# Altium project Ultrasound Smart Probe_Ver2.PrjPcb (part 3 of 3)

## Sheet Sht07--High Voltage Power Supply.SchDoc: HVPS
size 431 x 279 mm; Date: Not shown in title block; ApprovedBy: Not shown in title block; CheckedBy: Not shown in title block; Author: Not shown in title block; CompanyName: Not shown in title block; DrawnBy: Bill.Xu; Engineer: Bill.Xu; Organization: Not shown in title block; Address1: Not shown in title block; Address2: Not shown in title block; Address3: Not shown in title block; Address4: Not shown in title block; DocumentNumber: 1; Revision: Use project parameter SCH_Rev; SheetNumber: 7; SheetTotal: 7; PageSetup: Record=PageOptions¦CenterHorizontal=True¦CenterVertical=True¦PrintScale=1.00¦XCorrection=1.00¦YCorrection=1.00¦PrintKind=0¦BorderSize=5000000¦LeftOffset=0¦BottomOffset=0¦Orientation=2¦PaperLength=1000¦PaperWidth=1000¦Scale=100¦PaperSource=15¦PrintQuality=600¦MediaType=1¦DitherType=10¦PaperKind=Letter¦PrintScaleMode=1
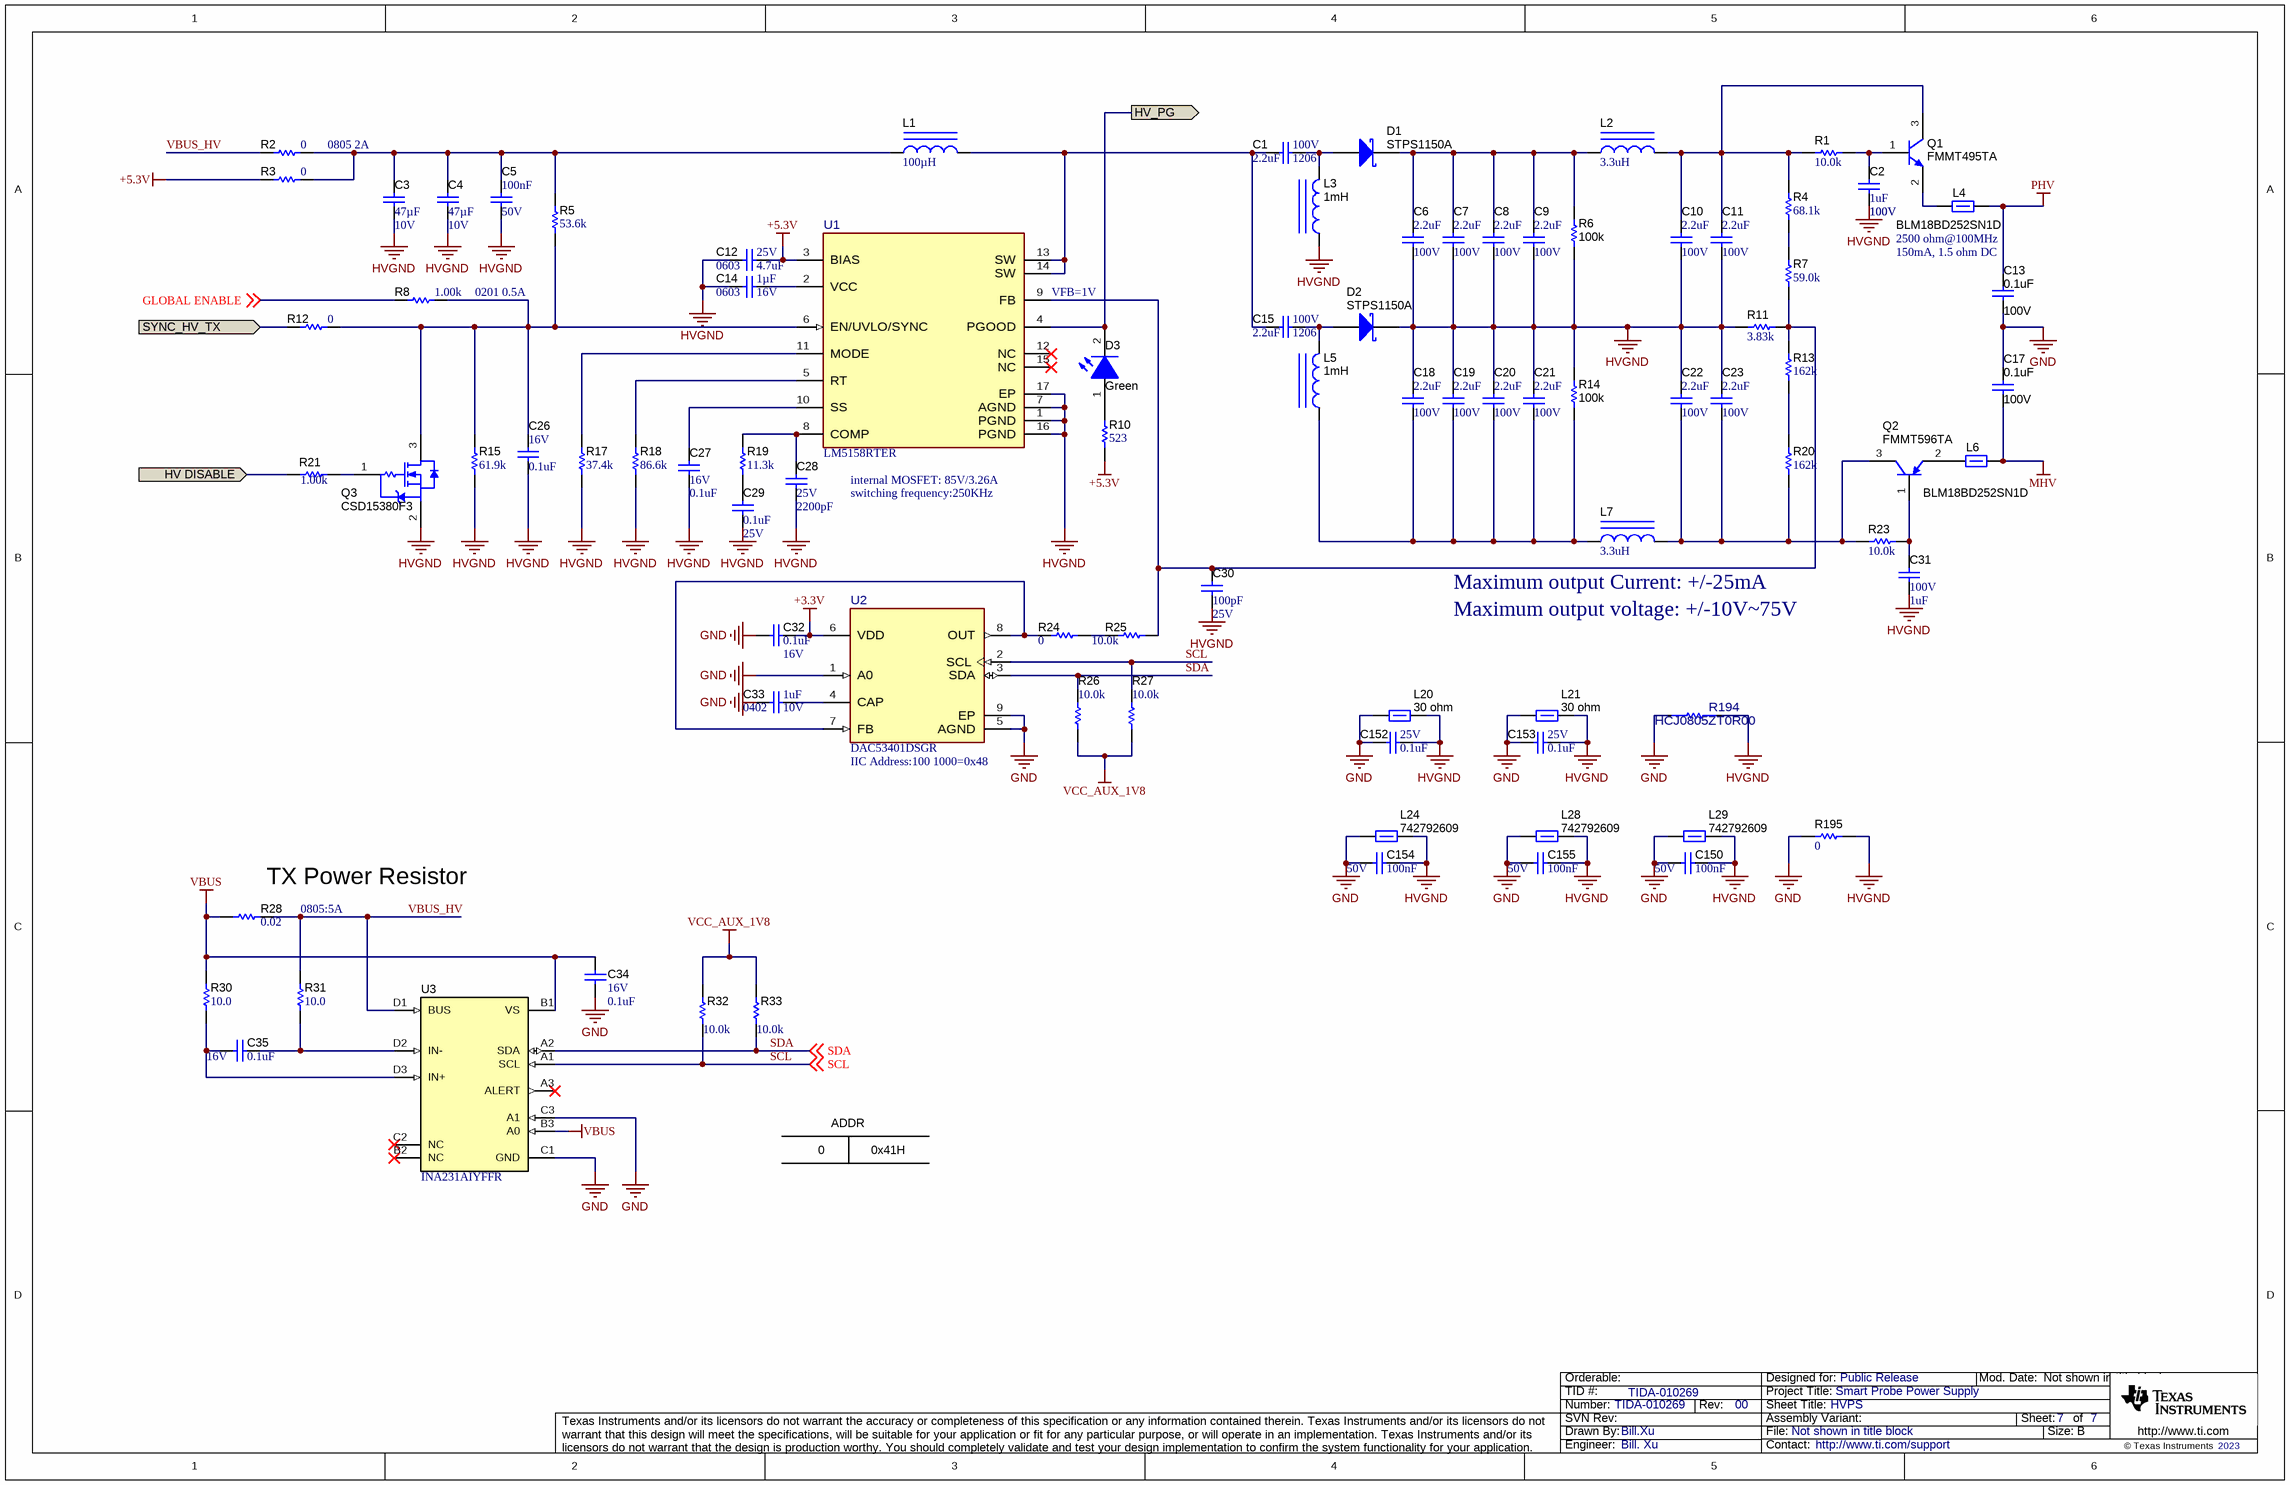
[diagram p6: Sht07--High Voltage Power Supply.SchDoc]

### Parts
C1  VDC_V: 100V  ValueDisplayed: 2.2uF  [1206_180]  (hidden comment: C3216X7S2A225K160AB)
C2  VDC_V: 100V  ValueDisplayed: 1uF  [0805_HV]  (hidden comment: C2012X7S2A105K125AB)
C3  VDC_V: 10V  ValueDisplayed: 47µF  [0805_HV]  (hidden comment: GRM21BR61A476ME15L)
C4  VDC_V: 10V  ValueDisplayed: 47µF  [0805_HV]  (hidden comment: GRM21BR61A476ME15L)
C5  Cap_F: 100nF  VDC_V: 50V  [0603]  (hidden comment: 885012206095)
C6  VDC_V: 100V  ValueDisplayed: 2.2uF  [1206_180]  (hidden comment: C3216X7S2A225K160AB)
C7  VDC_V: 100V  ValueDisplayed: 2.2uF  [1206_180]  (hidden comment: C3216X7S2A225K160AB)
C8  VDC_V: 100V  ValueDisplayed: 2.2uF  [1206_180]  (hidden comment: C3216X7S2A225K160AB)
C9  VDC_V: 100V  ValueDisplayed: 2.2uF  [1206_180]  (hidden comment: C3216X7S2A225K160AB)
C10  VDC_V: 100V  ValueDisplayed: 2.2uF  [1206_180]  (hidden comment: C3216X7S2A225K160AB)
C11  VDC_V: 100V  ValueDisplayed: 2.2uF  [1206_180]  (hidden comment: C3216X7S2A225K160AB)
C12  VDC_V: 25V  ValueDisplayed: 4.7uF  [0603]  (hidden comment: GRM188C81E475KE11D)
C13  VDC_V: 100V  ValueDisplayed: 0.1uF  [0603]  (hidden comment: GRM188R72A104KA35J)
C14  Cap_F: 1µF  VDC_V: 16V  [0603]  (hidden comment: GCM188R71C105KA64J)
C15  VDC_V: 100V  ValueDisplayed: 2.2uF  [1206_180]  (hidden comment: C3216X7S2A225K160AB)
C17  VDC_V: 100V  ValueDisplayed: 0.1uF  [0603]  (hidden comment: GRM188R72A104KA35J)
C18  VDC_V: 100V  ValueDisplayed: 2.2uF  [1206_180]  (hidden comment: C3216X7S2A225K160AB)
C19  VDC_V: 100V  ValueDisplayed: 2.2uF  [1206_180]  (hidden comment: C3216X7S2A225K160AB)
C20  VDC_V: 100V  ValueDisplayed: 2.2uF  [1206_180]  (hidden comment: C3216X7S2A225K160AB)
C21  VDC_V: 100V  ValueDisplayed: 2.2uF  [1206_180]  (hidden comment: C3216X7S2A225K160AB)
C22  VDC_V: 100V  ValueDisplayed: 2.2uF  [1206_180]  (hidden comment: C3216X7S2A225K160AB)
C23  VDC_V: 100V  ValueDisplayed: 2.2uF  [1206_180]  (hidden comment: C3216X7S2A225K160AB)
C26  VDC_V: 16V  ValueDisplayed: 0.1uF  [0201_033]  (hidden comment: C0603X6S1C104K030BC)
C27  VDC_V: 16V  ValueDisplayed: 0.1uF  [0201_033]  (hidden comment: C0603X6S1C104K030BC)
C28  VDC_V: 25V  ValueDisplayed: 2200pF  [0402]  (hidden comment: GRM155R71E222KA01D)
C29  VDC_V: 25V  ValueDisplayed: 0.1uF  [0402]  (hidden comment: GRM155R61E104KA87D)
C30  VDC_V: 25V  ValueDisplayed: 100pF  [0201_033]  (hidden comment: GRM033R71E101JA01D)
C31  VDC_V: 100V  ValueDisplayed: 1uF  [0805_HV]  (hidden comment: C2012X7S2A105K125AB)
C32  VDC_V: 16V  ValueDisplayed: 0.1uF  [0201_033]  (hidden comment: C0603X6S1C104K030BC)
C33  VDC_V: 10V  ValueDisplayed: 1uF  [0402]  (hidden comment: GRM155R61A105KE15D)
C34  VDC_V: 16V  ValueDisplayed: 0.1uF  [0201_033]  (hidden comment: C0603X6S1C104K030BC)
C35  VDC_V: 16V  ValueDisplayed: 0.1uF  [0201_033]  (hidden comment: C0603X6S1C104K030BC)
C150  Cap_F: 100nF  VDC_V: 50V  [0603]  (hidden comment: 885012206095)
C152  VDC_V: 25V  ValueDisplayed: 0.1uF  [0402]  (hidden comment: GRM155R61E104KA87D)
C153  VDC_V: 25V  ValueDisplayed: 0.1uF  [0402]  (hidden comment: GRM155R61E104KA87D)
C154  Cap_F: 100nF  VDC_V: 50V  [0603]  (hidden comment: 885012206095)
C155  Cap_F: 100nF  VDC_V: 50V  [0603]  (hidden comment: 885012206095)
D1  STPS1150A  [SMA]
D2  STPS1150A  [SMA]
D3  value Green  [LTST-C193_Green]  (hidden comment: LTST-C193KGKT-5A)
L1  ValueDisplayed: 100µH  [WE-LQS_8040]  (hidden comment: 74404084101)
L2  ValueDisplayed: 3.3uH  [WE-PMI_0806HS]  (hidden comment: 74479776233)
L3  ValueDisplayed: 1mH  [WE-TPC_4828]  (hidden comment: 744043102)
L4  BLM18BD252SN1D  [0603]
L5  ValueDisplayed: 1mH  [WE-TPC_4828]  (hidden comment: 744043102)
L6  BLM18BD252SN1D  [0603]
L7  ValueDisplayed: 3.3uH  [WE-PMI_0806HS]  (hidden comment: 74479776233)
L20  ValueDisplayed: 30 ohm  [0603]  (hidden comment: 742792609)
L21  ValueDisplayed: 30 ohm  [0603]  (hidden comment: 742792609)
L24  742792609  [0603]
L28  742792609  [0603]
L29  742792609  [0603]
Q1  FMMT495TA  [SOT-23]
Q2  FMMT596TA  [SOT-23]
Q3  CSD15380F3  [YJM0003A]
R1  ValueDisplayed: 10.0k  [0402]  (hidden comment: RK73H1ETTP1002F)
R2  ValueDisplayed: 0  [0805_HV]  (hidden comment: RC0805JR-070RL)
R3  ValueDisplayed: 0  [0805_HV]  (hidden comment: RC0805JR-070RL)
R4  ValueDisplayed: 68.1k  [0603]  (hidden comment: RC0603FR-0768K1L)
R5  ValueDisplayed: 53.6k  [0201]  (hidden comment: RC0201FR-0753K6L)
R6  ValueDisplayed: 100k  [0603]  (hidden comment: CRCW0603100KJNEAC)
R7  ValueDisplayed: 59.0k  [0603]  (hidden comment: RC0603FR-0759KL)
R8  ValueDisplayed: 1.00k  [0201]  (hidden comment: RC0201FR-7D1KL)
R10  ValueDisplayed: 523  [0402]  (hidden comment: CRCW0402523RFKED)
R11  ValueDisplayed: 3.83k  [0402]  (hidden comment: CRCW04023K83FKED)
R12  ValueDisplayed: 0  [0201]  (hidden comment: CRCW02010000Z0ED)
R13  ValueDisplayed: 162k  [0603]  (hidden comment: RC0603FR-07162KL)
R14  ValueDisplayed: 100k  [0603]  (hidden comment: CRCW0603100KJNEAC)
R15  ValueDisplayed: 61.9k  [0201]  (hidden comment: RC0201FR-0761K9L)
R17  ValueDisplayed: 37.4k  [0201]  (hidden comment: RC0201FR-0737K4L)
R18  ValueDisplayed: 86.6k  [0201]  (hidden comment: RC0201FR-0786K6L)
R19  ValueDisplayed: 11.3k  [0402]  (hidden comment: CRCW040211K3FKED)
R20  ValueDisplayed: 162k  [0603]  (hidden comment: RC0603FR-07162KL)
R21  ValueDisplayed: 1.00k  [0201]  (hidden comment: RC0201FR-7D1KL)
R23  ValueDisplayed: 10.0k  [0402]  (hidden comment: RK73H1ETTP1002F)
R24  ValueDisplayed: 0  [0201]  (hidden comment: CRCW02010000Z0ED)
R25  ValueDisplayed: 10.0k  [0201]  (hidden comment: RC0201FS-7D10KL)
R26  ValueDisplayed: 10.0k  [0201]  (hidden comment: RC0201FS-7D10KL)
R27  ValueDisplayed: 10.0k  [0201]  (hidden comment: RC0201FS-7D10KL)
R28  ValueDisplayed: 0.02  [WSLP0805]  (hidden comment: WSLP0805R0200FEB)
R30  ValueDisplayed: 10.0  [0201]  (hidden comment: RC0201FR-7D10RL)
R31  ValueDisplayed: 10.0  [0201]  (hidden comment: RC0201FR-7D10RL)
R32  ValueDisplayed: 10.0k  [0201]  (hidden comment: RC0201FS-7D10KL)
R33  ValueDisplayed: 10.0k  [0201]  (hidden comment: RC0201FS-7D10KL)
R194  HCJ0805ZT0R00  [FP-HCJ0805ZT0R00_0805-MFG]
R195  ValueDisplayed: 0  [0603]  (hidden comment: RC0603JR-070RL)
U1  LM5158RTER  [RTE0016K-MFG]
U2  DAC53401DSGR  [DSG0008A-MFG]
U3  INA231AIYFFR  [YFF0012AKAD]

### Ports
HV DISABLE (in), HV_PG (out), SYNC_HV_TX (in)

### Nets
+3.3V: C32.2 U2.6(VDD)
+5.3V: C12.1 R3.1 R10.1 U1.3(BIAS)
GND: C13.2 C17.1 C32.1 C33.2 C34.2 C150.2 C152.1 C153.1 C154.2 C155.2 L20.1 L21.1 L24.1 L28.1 L29.1 R194.1 R195.1 U2.1(A0) U2.5(AGND) U2.9(EP) U3.C1(GND) U3.C3(A1)
HVGND: C2.2 C3.2 C4.2 C5.2 C6.2 C7.2 C8.2 C9.2 C10.2 C11.2 C12.2 C14.2 C18.1 C19.1 C20.1 C21.1 C22.1 C23.1 C26.1 C27.1 C28.2 C29.2 C30.2 C31.2 C150.1 C152.2 C153.2 C154.1 C155.1 D2.1(K) L3.1 L20.2 L21.2 L24.2 L28.2 L29.2 Q3.2(S) R6.1 R11.1 R14.2 R15.1 R17.1 R18.1 R194.2 R195.2 U1.1(PGND) U1.7(AGND) U1.16(PGND) U1.17(EP)
MHV: C17.2 L6.2
PHV: C13.1 L4.2
VBUS: C34.1 R28.1 R30.2 U3.B1(VS) U3.B3(A0)
VCC_AUX_1V8: R26.1 R27.1 R32.2 R33.2
GLOBAL ENABLE: R8.1 ; off-sheet GLOBAL ENABLE
HV DISABLE: R21.1 ; port HV DISABLE
HV_PG: D3.2(K) U1.4(PGOOD) ; port HV_PG
SCL: R27.2 R32.1 U2.2(SCL) U3.A1(SCL) ; off-sheet SCL
SDA: R26.2 R33.1 U2.3(SDA) U3.A2(SDA) ; off-sheet SDA
SYNC_HV_TX: R12.1 ; port SYNC_HV_TX
VBUS_HV: R2.1 R28.2 R31.2 U3.D1(BUS)
NetC1_1: C1.1 C15.1 L1.2 U1.13(SW) U1.14(SW)
NetC1_2: C1.2 D1.2(A) L3.2
NetC2_1: C2.1 Q1.1(B) R1.2
NetC3_1: C3.1 C4.1 C5.1 L1.1 R2.2 R3.2 R5.2
NetC6_1: C6.1 C7.1 C8.1 C9.1 D1.1(K) L2.1 R6.2
NetC10_1: C10.1 C11.1 L2.2 Q1.3(C) R1.1 R4.2
NetC14_1: C14.1 U1.2(VCC)
NetC15_2: C15.2 D2.2(A) L5.2
NetC18_2: C18.2 C19.2 C20.2 C21.2 L5.1 L7.1 R14.1
NetC22_2: C22.2 C23.2 L7.2 Q2.3(C) R20.1 R23.1
NetC26_2: C26.2 Q3.3(D) R5.1 R8.2 R12.2 R15.2 U1.6(EN/UVLO/SYNC)
NetC27_2: C27.2 U1.10(SS)
NetC28_1: C28.1 R19.2 U1.8(COMP)
NetC29_1: C29.1 R19.1
NetC30_1: C30.1 R7.1 R11.2 R13.2 R25.1 U1.9(FB)
NetC31_1: C31.1 Q2.1(B) R23.2
NetC33_1: C33.1 U2.4(CAP)
NetC35_1: C35.1 R31.1 U3.D2(IN-)
NetC35_2: C35.2 R30.1 U3.D3(IN+)
NetD3_1: D3.1(A) R10.2
NetL4_1: L4.1 Q1.2(E)
NetL6_1: L6.1 Q2.2(E)
NetQ3_1: Q3.1(G) R21.2
NetR4_1: R4.1 R7.2
NetR13_1: R13.1 R20.2
NetR17_2: R17.2 U1.11(MODE)
NetR18_2: R18.2 U1.5(RT)
NetR24_1: R24.1 U2.7(FB) U2.8(OUT)
NetR24_2: R24.2 R25.2

Not connected (* = marked no-connect by the designer): U1 12(NC)* 15(NC)*; U3 A3(ALERT)* B2(NC)* C2(NC)*

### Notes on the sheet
- 0805 2A
- (near C1) 1206
- (near C2) 100V
- 0201 0.5A
- (near C14) 0603
- (near C12) 0603
- (near U1) VFB=1V
- 2500 ohm@100MHz
- 150mA, 1.5 ohm DC
- (near C15) 1206
- internal MOSFET: 85V/3.26A
- switching frequency:250KHz
- (near L7) Maximum output Current: +/-25mA
- Maximum output voltage: +/-10V~75V
- (near C33) 0402
- (near U2) IIC Address:100 1000=0x48
- (near R28) TX Power Resistor
- (near R28) 0805:5A
- 0
- ADDR
- 0x41H

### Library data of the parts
C1 C6-C11 C15 C18-C23 = CMP-0008724-2: CAP, CERM, 2.2 uF, 100 V, +/- 10%, X7S, 1206; Manufacturer: TDK; TaMin_C: -55°C; ESR_ohm: 5.718m; Polarized: N; SizeAreaWB_mm2: 10.92; Value1: 0.005718 ohm; U/M: EA; Value: 2.2uF; TaMax_C: 125°C; SizeZ_mm: 1.8; SizeX_mm: 3.2; SizeY_mm: 1.6; SizeArea_mm2: 5.12; Cap_F: 2.2µF; IRMS_A: 3.03632A; AEC Category: Q200
C2 = CMP-0007891-2: CAP, CERM, 1 uF, 100 V, +/- 10%, X7S, 0805; Manufacturer: TDK; TaMin_C: -55°C; ESR_ohm: 8.255m; Polarized: N; SizeAreaWB_mm2: 6.75; Value1: 0.008255 ohm; U/M: EA; Value: 1uF; TaMax_C: 125°C; SizeZ_mm: 1.45; SizeX_mm: 2; SizeY_mm: 1.25; Cap_Case: 0805; SizeArea_mm2: 2.5; Cap_F: 1µF; IRMS_A: 2.2744A; AEC Category: Q200
C3 C4 = CMP-0078699-1: CAP, CERM, 47 µF, 10 V,+/- 20%, X5R, 0805; Manufacturer: MuRata; TaMin_C: -55°C; Polarized: N; Green_Lifecycle: Active; SizeAreaWB_mm2: 6.75; Green_REACh: Passed; U/M: EA; Value: 47uF; TaMax_C: 85°C; SizeZ_mm: 1.45; SizeX_mm: 2; SizeY_mm: 1.25; Cap_Case: 0805; SizeArea_mm2: 2.5; AEC Category: Q200
C5 C150 C154 C155 = CMP-0006837-2: CAP, CERM, 0.1 uF, 50 V, +/- 10%, X7R, 0603; Manufacturer: Wurth Elektronik; TaMin_C: -55°C; Polarized: N; SizeAreaWB_mm2: 4.68; Value1: Unknown; U/M: EA; Value: 0.1uF; TaMax_C: 125°C; SizeZ_mm: 1; SizeX_mm: 1.6; SizeY_mm: 0.8; SizeArea_mm2: 1.28; AEC Category: Q200
C12 = CMP-0007297-3: CAP, CERM, 4.7 uF, 25 V, +/- 10%, X6S, 0603; Manufacturer: MuRata; TaMin_C: -55°C; Polarized: N; SizeAreaWB_mm2: 4.68; Value1: Unknown; U/M: EA; Value: 4.7uF; TaMax_C: 105°C; SizeZ_mm: 1; SizeX_mm: 1.6; SizeY_mm: 0.8; SizeArea_mm2: 1.28; Cap_F: 4.7µF; AEC Category: Q200
C13 C17 = CMP-0007470-5: CAP, CERM, 0.1 uF, 100 V, +/- 10%, X7R, 0603; Manufacturer: MuRata; TaMin_C: -55°C; Polarized: N; SizeAreaWB_mm2: 4.68; Value1: Unknown; U/M: EA; Value: 0.1uF; TaMax_C: 125°C; SizeZ_mm: 1; SizeX_mm: 1.6; SizeY_mm: 0.8; SizeArea_mm2: 1.28; Cap_F: 100nF; AEC Category: Q200
C14 = CMP-0079154-1: CAP, CERM, 1 µF, 16 V,+/- 10%, X7R, AEC-Q200 Grade 1, 0603; Manufacturer: MuRata; SizeAreaWB_mm2: 4.68; SizeArea_mm2: 1.28; AEC Qualified: Y; AEC Category: Q200; Value: 1uF; TaMax_C: 125°C; SizeZ_mm: 1; Polarized: N; TaMin_C: -55°C; SizeY_mm: 0.8; U/M: EA; SizeX_mm: 1.6
C26 C27 C32 C34 C35 = CMP-0009637-1: CAP, CERM, 0.1 uF, 16 V, +/- 10%, X6S, 0201; Manufacturer: TDK; TaMin_C: -55°C; Polarized: N; SizeAreaWB_mm2: 2.08; Value1: Unknown; U/M: EA; Value: 0.1uF; TaMax_C: 105°C; SizeZ_mm: 0.33; SizeX_mm: 0.6; SizeY_mm: 0.3; Cap_Case: 0201; SizeArea_mm2: 0.18; Cap_F: 100nF; AEC Category: Q200
C28 = CMP-0006663-2: CAP, CERM, 2200 pF, 25 V, +/- 10%, X7R, 0402; Manufacturer: MuRata; TaMin_C: -55°C; Polarized: N; SizeAreaWB_mm2: 3; Value1: Unknown; U/M: EA; Value: 2200pF; TaMax_C: 125°C; SizeZ_mm: 0.6; SizeX_mm: 1; SizeY_mm: 0.5; Cap_F: 2.2nF; AEC Category: Q200
C29 C152 C153 = CMP-0006607-1: CAP, CERM, 0.1 uF, 25 V, +/- 10%, X5R, 0402; Manufacturer: MuRata; TaMin_C: -55°C; Polarized: N; SizeAreaWB_mm2: 3; Value1: Unknown; U/M: EA; Value: 0.1uF; TaMax_C: 85°C; SizeZ_mm: 0.6; SizeX_mm: 1; SizeY_mm: 0.5; Cap_F: 100nF; AEC Category: Q200
C30 = CMP-0009762-1: CAP, CERM, 100 pF, 25 V, +/- 5%, C0G/NP0, 0201; Manufacturer: MuRata; TaMin_C: -55°C; Polarized: N; SizeAreaWB_mm2: 2.08; Value1: Unknown; U/M: EA; Value: 100pF; TaMax_C: 125°C; SizeZ_mm: 0.33; SizeX_mm: 0.6; SizeY_mm: 0.3; Cap_Case: 0201; SizeArea_mm2: 0.18; AEC Category: Q200
C31 = CMP-0007891-1: CAP, CERM, 1 uF, 100 V, +/- 10%, X7S, 0805; Manufacturer: TDK; TaMin_C: -55°C; ESR_ohm: 8.255m; Polarized: N; SizeAreaWB_mm2: 6.75; Value1: 0.008255 ohm; U/M: EA; Value: 1uF; TaMax_C: 125°C; SizeZ_mm: 1.45; SizeX_mm: 2; SizeY_mm: 1.25; Cap_Case: 0805; SizeArea_mm2: 2.5; Cap_F: 1µF; IRMS_A: 2.2744A; AEC Category: Q200
C33 = CMP-0006563-2: CAP, CERM, 1 uF, 10 V, +/- 10%, X5R, 0402; Manufacturer: MuRata; TaMin_C: -55°C; Polarized: N; SizeAreaWB_mm2: 3; Value1: Unknown; U/M: EA; Value: 1uF; TaMax_C: 85°C; SizeZ_mm: 0.6; SizeX_mm: 1; SizeY_mm: 0.5; Cap_F: 1µF; AEC Category: Q200
D1 D2 = CMP-0028752-1: Diode, Schottky, 150 V, 1 A, SMA; Manufacturer: STMicroelectronics; Io_A: 1A; Green_Lifecycle: Not Set; SizeAreaWB_mm2: 37.3428; Vr_V: 150V; Green_REACh: Incomplete; TJmax_C: 175°C; U/M: EA; Value: 150V; SizeZ_mm: 2.87; SizeX_mm: 5.59; SizeY_mm: 2.92; Vf_V: 780mV; Value2: 0.78V; SizeArea_mm2: 16.3228; AEC Qualified: N; AEC Category: Q101; RJC_CperW: 30
D3 = CMP-0079921-3: LED, Green, SMD; Manufacturer: Lite-On; SizeArea_mm2: 1.28; Vf_V: 2V; SizeX_mm: 1.6; SizeZ_mm: 0.45; Type: AlInGaP; SizeY_mm: 0.8; Value1: W; Tjmax_C: 85°C; Io_A: 5mA; SizeAreaWB_mm2: 4.68
L1 = CMP-0086317-1: Inductor, Shielded, Ferrite, 100 µH, 1.2 A, 0.377 ohm, SMD; Manufacturer: Wurth Elektronik; Value: 100uH; Imax_A: 1.2A; SizeArea_mm2: 64; SizeX_mm: 8; Isat: 1.5A @ 20% inductance drop; SizeZ_mm: 4.2; SizeAreaWB_mm2: 100; DCR_ohm: 0.377; AEC Category: Q200; AEC Qualified: N; Irms: 1.2A @ 40C rise
L2 L7 = CMP-0064322-1: Inductor, Shielded Drum Core, Metal Composite, 3.3 uH, 0.26 A, 0.13 ohm, SMD; Manufacturer: Wurth Elektronik; Isat: 0.26A @ 30% inductance drop; Irms: 1.1A @ 40C rise; Green_Lifecycle: Active; SizeAreaWB_mm2: 7.8; DCR_ohm: 0.13; Green_REACh: Passed; Value: 3.3uH; Imax_A: 260mA; SizeZ_mm: 1; SizeX_mm: 2; SizeY_mm: 1.6; Value2: 0.26A; SizeArea_mm2: 3.2; Ind_H: 3.3µH; AEC Category: Q200
L3 L5 = CMP-0064699-2: Inductor, Shielded Drum Core, Metal Composite, 1mH, 0.08 A, 5.4 ohm, SMD; Manufacturer: Wurth Elektronik; Isat: 0.08A @ 35% inductance drop; Irms: 0.14A @ 30C rise; Green_Lifecycle: Active; SizeAreaWB_mm2: 33.64; DCR_ohm: 5.4; Green_REACh: Passed; Value1: 5.4 ohm; Imax_A: 0.08A; SizeZ_mm: 3; SizeX_mm: 4.8; SizeArea_mm2: 23.04; Ind_H: 470µH; AEC Category: Q200
L4 L6 = CMP-0003346-2: Ferrite Bead, 2500 ohm @ 100 MHz, 0.15 A, 0603; Manufacturer: MuRata; ZTyp@100MHz_Ohm: 2.5k; SizeAreaWB_mm2: 4.68; DCR_ohm: 1.5; Value1: 1.5 ohm; Imax_A: 150mA; SizeZ_mm: 1; SizeX_mm: 1.6; SizeY_mm: 0.8; Value2: 0.15A; SizeArea_mm2: 1.28
L20 L21 = 742792609: Ferrite Bead, 30 ohm @ 100 MHz, 3 A, 0603; Manufacturer: Wurth Elektronik; Value: 30 ohm; Imax_A: 3; DCR_ohm: 0.04; Value1: 0.04 ohm; Value2: 3A; SizeAreaWB_mm2: 4.68; SizeArea_mm2: 1.28; SizeX_mm: 1.6; SizeY_mm: 0.8; SizeZ_mm: 1; ZTyp@100MHz_Ohm: 30; Ztyp@1GHz_Ohm: 40.472; Green_Lifecycle: Active; Green_REACh: Passed
L24 L28 L29 = CMP-0003180-2: Ferrite Bead, 30 ohm @ 100 MHz, 3 A, 0603; Manufacturer: Wurth Elektronik; Ztyp@1GHz_Ohm: 40.472; ZTyp@100MHz_Ohm: 30; SizeAreaWB_mm2: 4.68; DCR_ohm: 40m; Value1: 0.04 ohm; Value: 30 ohm; Imax_A: 3A; SizeZ_mm: 1; SizeX_mm: 1.6; SizeY_mm: 0.8; SizeArea_mm2: 1.28
Q1 = CMP-0074710-1: Transistor, NPN, 150 V, 1 A, AEC-Q101, SOT-23; Manufacturer: Diodes Inc.; TaMin_C: -55°C; HfeMax: 300.0; SizeAreaWB_mm2: 14.0; Value1: 1 A; Vceo_V: 150V; U/M: EA; Value: 150 V; TaMax_C: 150°C; IcRated_A: 1A; SizeZ_mm: 1.1; SizeX_mm: 2.5; SizeY_mm: 3.0; SizeArea_mm2: 7.5; CompType: BJT; PNP: 0.0; AEC Qualified: Y; NPN: 1.0; Vcesat1_V: 3dV; AEC Category: Q101
Q2 = CMP-0000370-2: Transistor, PNP, 200 V, 0.3 A, SOT-23; Manufacturer: Diodes Inc.; TaMax_C: 150°C; Value2: 300; Value1: 0.3 A; Vcesat1_V: 2dV; SizeX_mm: 2.5; SizeY_mm: 3; TaMin_C: -55°C; IcRated_A: 3dA; CompType: BJT; SizeZ_mm: 1.1; AEC Qualified: N; Value: 200 V; SizeArea_mm2: 7.5; NPN: 0; Vceo_V: 200V; PNP: 1; AEC Category: Q101; SizeAreaWB_mm2: 14; U/M: EA
Q3 = CMP-0000206-2: MOSFET, N-CH, 20 V, 0.5 A, YJM0003A (PICOSTAR-3); Alternate Manufacturer: None; Manufacturer: Texas Instruments; SizeZ_mm: 0.35; ChType: N; Value2: 0.216 nC; Value1: 1.4; VdsMax_V: 20V; SizeX_mm: 0.69; SizeY_mm: 0.6; Vgs_V: 10V; Value: 20V; Rdson45_ohm: 1.46; SizeArea_mm2: 0.414; AEC Category: Q101; IdsMax_A: 500mA; SizeAreaWB_mm2: 2.704; U/M: EA; QgTyp_nC: 0.216
R1 R23 = CMP-0026748-1: RES, 10.0 k, 1%, 0.063 W, AEC-Q200 Grade 0, 0402; Manufacturer: KOA Speer; Power_W: 63mW; TempCo: 100 ppm/C; Value_Code: 10k0; U/M: EA; Value: 10.0k; EIA_Code: E96; Res_ohm: 10k; SizeX_mm: 1; SizeY_mm: 0.5; SizeZ_mm: 0.6; Value2: 0.063W; AEC Qualified: Y; VDC_V: 50V; AEC Grade: 0; AEC Category: Q200
R2 R3 = CMP-0020803-2: RES, 0, 5%, 0.125 W, 0805; Manufacturer: Yageo America; Power_W: 125mW; TempCo: 200 ppm/C; Value_Code: 0000; U/M: EA; Value: 0; EIA_Code: E24; SizeX_mm: 2; SizeY_mm: 1.25; SizeZ_mm: 1.45; Value2: 0.125W; SizeArea_mm2: 2.5; VDC_V: 150V; AEC Category: Q200
R4 = CMP-0023238-5: RES, 68.1 k, 1%, 0.1 W, 0603; Manufacturer: Yageo; Power_W: 100mW; TempCo: 100 ppm/C; Value_Code: 68k1; Value: 68.1k; EIA_Code: E96; SizeX_mm: 1.6; SizeY_mm: 0.8; SizeZ_mm: 1; Value2: 0.1W; SizeArea_mm2: 1.28; AEC Qualified: N; VDC_V: 75V; AEC Category: Q200; SizeAreaWB_mm2: 4.68
R5 = CMP-0027766-1: RES, 53.6 k, 1%, 0.05 W, 0201; Manufacturer: Yageo America; Power_W: 50mW; TempCo: 200 ppm/C; Value_Code: 53k6; U/M: EA; Value: 53.6k; EIA_Code: E96; SizeX_mm: 0.6; SizeY_mm: 0.3; SizeZ_mm: 0.26; Value2: 0.05W; SizeArea_mm2: 0.18; AEC Qualified: N; VDC_V: 25V; AEC Category: Q200
R6 R14 = CMP-0082530-1: RES, 100 k, 1%, 0.1 W, 0603; Manufacturer: Panasonic; PartNumber: ERJ-3EKF1003V; Power_W: 100mW; TempCo: 200 ppm/C; SizeAreaWB_mm2: 4.68; Value1: 5%; Value: 100k; EIA_Code: E24; SizeX_mm: 1.6; SizeY_mm: 0.8; SizeZ_mm: 1; Value2: 0.1W; SizeArea_mm2: 1.28; AEC Qualified: N; VDC_V: 75V; AEC Category: Q200
R7 = CMP-0023195-5: RES, 59.0 k, 1%, 0.1 W, 0603; Manufacturer: Yageo; Power_W: 100mW; TempCo: 100 ppm/C; Value_Code: 59k0; Value: 59.0k; EIA_Code: E96; Res_ohm: 59k; SizeX_mm: 1.6; SizeY_mm: 0.8; SizeZ_mm: 1; Value2: 0.1W; SizeArea_mm2: 1.28; AEC Qualified: N; VDC_V: 75V; AEC Category: Q200; SizeAreaWB_mm2: 4.68
R8 R21 = CMP-0027973-1: RES, 1.00 k, 1%, 0.05 W, 0201; Manufacturer: Yageo America; Power_W: 50mW; TempCo: 200 ppm/C; Value_Code: 1k00; U/M: EA; Value: 1.00k; EIA_Code: E96; Res_ohm: 1k; SizeX_mm: 0.6; SizeY_mm: 0.3; SizeZ_mm: 0.26; Value2: 0.05W; SizeArea_mm2: 0.18; AEC Qualified: N; VDC_V: 25V; AEC Category: Q200
R10 = CMP-0026440-2: RES, 523, 1%, 0.063 W, AEC-Q200 Grade 0, 0402; Manufacturer: Vishay-Dale; Power_W: 63mW; TempCo: 100 ppm/C; Value_Code: 523R; Value: 523; EIA_Code: E96; SizeX_mm: 1; SizeY_mm: 0.5; SizeZ_mm: 0.6; Value2: 0.063W; AEC Qualified: Y; VDC_V: 50V; AEC Category: Q200; AEC Grade: 0
R11 = CMP-0026339-2: RES, 3.83 k, 1%, 0.063 W, AEC-Q200 Grade 0, 0402; Manufacturer: Vishay-Dale; Power_W: 63mW; TempCo: 100 ppm/C; Value_Code: 3k83; Value: 3.83k; EIA_Code: E96; SizeX_mm: 1; SizeY_mm: 0.5; SizeZ_mm: 0.6; Value2: 0.063W; AEC Qualified: Y; VDC_V: 50V; AEC Category: Q200; AEC Grade: 0
R12 R24 = CMP-0027008-1: RES, 0, 5%, 0.05 W, 0201; Manufacturer: Vishay-Dale; Power_W: 50mW; TempCo: ppm/C; Value_Code: 0000; U/M: EA; Value: 0; EIA_Code: E24; SizeX_mm: 0.6; SizeY_mm: 0.3; SizeZ_mm: 0.26; Value2: 0.05W; SizeArea_mm2: 0.18; AEC Qualified: N; AEC Category: Q200
R13 R20 = CMP-0022822-4: RES, 162 k, 1%, 0.1 W, 0603; Manufacturer: Yageo; Power_W: 100mW; TempCo: 100 ppm/C; Value: 162k; EIA_Code: E96; SizeX_mm: 1.6; SizeY_mm: 0.8; SizeZ_mm: 1; Value2: 0.1W; SizeArea_mm2: 1.28; AEC Qualified: N; VDC_V: 75V; AEC Category: Q200; SizeAreaWB_mm2: 4.68
R15 = CMP-0027811-1: RES, 61.9 k, 1%, 0.05 W, 0201; Manufacturer: Yageo America; Power_W: 50mW; TempCo: 200 ppm/C; Value_Code: 61k9; U/M: EA; Value: 61.9k; EIA_Code: E96; SizeX_mm: 0.6; SizeY_mm: 0.3; SizeZ_mm: 0.26; Value2: 0.05W; SizeArea_mm2: 0.18; AEC Qualified: N; VDC_V: 25V; AEC Category: Q200
R17 = CMP-0027638-1: RES, 37.4 k, 1%, 0.05 W, 0201; Manufacturer: Yageo America; Power_W: 50mW; TempCo: 200 ppm/C; Value_Code: 37k4; U/M: EA; Value: 37.4k; EIA_Code: E96; SizeX_mm: 0.6; SizeY_mm: 0.3; SizeZ_mm: 0.26; Value2: 0.05W; SizeArea_mm2: 0.18; AEC Qualified: N; VDC_V: 25V; AEC Category: Q200
R18 = CMP-0027901-1: RES, 86.6 k, 1%, 0.05 W, 0201; Manufacturer: Yageo America; Power_W: 50mW; TempCo: 200 ppm/C; Value_Code: 86k6; U/M: EA; Value: 86.6k; EIA_Code: E96; SizeX_mm: 0.6; SizeY_mm: 0.3; SizeZ_mm: 0.26; Value2: 0.05W; SizeArea_mm2: 0.18; AEC Qualified: N; VDC_V: 25V; AEC Category: Q200
R19 = CMP-0025976-3: RES, 11.3 k, 1%, 0.063 W, AEC-Q200 Grade 0, 0402; Manufacturer: Vishay-Dale; Power_W: 63mW; TempCo: 100 ppm/C; Value_Code: 11k3; Value: 11.3k; EIA_Code: E96; SizeX_mm: 1; SizeY_mm: 0.5; SizeZ_mm: 0.6; Value2: 0.063W; AEC Qualified: Y; VDC_V: 50V; AEC Category: Q200; AEC Grade: 0
R25-R27 R32 R33 = CMP-0028071-1: RES SMD 10K OHM 1% 1/20W 0201; Manufacturer: Samsung Electro-Mechanics; PartNumber: RC0603F103CS; Power_W: 50mW; TempCo: 200 ppm/C; Value_Code: 10k0; U/M: EA; Value: 10.0k; EIA_Code: E96; SizeX_mm: 0.6; SizeY_mm: 0.3; SizeZ_mm: 0.26; Value2: 0.05W; SizeArea_mm2: 0.18; AEC Qualified: N; VDC_V: 25V; AEC Category: Q200
R28 = CMP-0021986-1: RES, 0.02, 1%, 0.5 W, 0805; Manufacturer: Vishay-Dale; Power_W: 500mW; TempCo: 75 ppm/C; Value_Code: R020; U/M: EA; Value: 0.02; EIA_Code: E96; Res_ohm: 20m; SizeX_mm: 2.03; SizeY_mm: 1.27; SizeZ_mm: 0.635; Value2: 0.5W; SizeArea_mm2: 2.5781; AEC Qualified: N; AEC Category: Q200
R30 R31 = CMP-0027946-1: RES, 10.0, 1%, 0.05 W, 0201; Manufacturer: Yageo America; Power_W: 50mW; TempCo: 350 ppm/C; Value_Code: 10R0; U/M: EA; Value: 10.0; EIA_Code: E96; Res_ohm: 10; SizeX_mm: 0.6; SizeY_mm: 0.3; SizeZ_mm: 0.26; Value2: 0.05W; SizeArea_mm2: 0.18; AEC Qualified: N; VDC_V: 25V; AEC Category: Q200
R194 = CMP-0091603-1: 0 Ohms Jumper 0.5W, 1/2W Chip Resistor 0805 (2012 Metric) Automotive AEC-Q200 Metal Foil; Manufacturer: Stackpole; Value: 0; SizeZ_mm: 0.85mm; Power: 500mW; AEC Grade: Grade 0; AEC Qualified: Yes
R195 = CMP-0025885-5: RES, 0, 5%, 0.1 W, 0603; Manufacturer: Yageo; Power_W: 100mW; TempCo: 200 ppm/C; Value_Code: 0000; Value: 0; EIA_Code: E24; SizeX_mm: 1.6; SizeZ_mm: 1; Value2: 0.1W; SizeArea_mm2: 1.28; AEC Qualified: N; VDC_V: 75V; AEC Category: Q200; SizeY_mm: 0.8; SizeAreaWB_mm2: 4.68
U1 = CMP-0092925-1: 2.2-MHz Wide VIN 85-V Boost/Sepic/Flyback Converter with Dual Random Spread Spectrum, 1.5A, WQFN16; Manufacturer: Texas Instruments; TaMax_C: +125°C; TJmax_C: +150°C; Standoff Height: 0mm; Number Of Outputs: 1; Max Duty Cycle: 96%; Switching Topology: Boost,Flyback,Other; Output Type: AdjustableProgrammable; Switching Frequency: 100-2200kHz; AEC Qualified: No; SizeZ_mm: 0.8mm; TaMin_C: -40°C; Output Voltage: 1.5-83V; Min Supply Voltage: 1.5V; Max Supply Voltage: 60V; Nominal Supply Current: 670uA
U2 = CMP-0091224-1: 10-Bit and 8-Bit, Voltage-Output Digital-to-Analog Converters With Nonvolatile Memory and PMBus™ Compatible I 2C Interface in Tiny 2 × 2 WSON; Manufacturer: Texas Instruments; Number Of Converters: 1; TJmax_C: +150°C; Min Supply Voltage: 1.71V; Interface: I2C; TaMin_C: -40°C; AEC Qualified: No; SizeZ_mm: 0.8mm; Resolution: 10bits; TaMax_C: +125°C; Max Supply Voltage: 5.5V; Standoff Height: 0mm; Sampling Rate: 25ksps; Nominal Supply Current: 0.5mA
U3 = CMP-0065450-1: 28-V, Bi-Directional, Zero-Drift, Low-/High-Side, I2C Out Current/Power Monitor w/ Alert in WCSP, YFF0012AKAD (DSBGA-12); Alternate PartNumber: INA231AIYFFT; Alternate Manufacturer: Texas Instruments; Green_Lifecycle: Active; SizeAreaWB_mm2: 6.313872; Green_REACh: Passed; U/M: EA; SizeZ_mm: 0.625; SizeX_mm: 1.388; SizeY_mm: 1.644; SizeArea_mm2: 2.281872; CompType: IC

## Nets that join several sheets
1V2_DVDD: Sht02--Input Output Connector (P1.19 P1.21), Sht05--TX-RX Supply 1.8V and 1.15V (C204.1 L27.2)
1V8_DVDD: Sht02--Input Output Connector (14 pins), Sht05--TX-RX Supply 1.8V and 1.15V (C25.1 C183.1 L22.2)
+5.3V: Sht05--TX-RX Supply 1.8V and 1.15V (C201.1 U28.10), Sht06--TX Supply +5V and -5V (8 pins), Sht07--High Voltage Power Supply (C12.1 R3.1 R10.1 U1.3)
AVDD_1P2: Sht02--Input Output Connector (P2.39 P2.40 P2.41 P2.42), Sht05--TX-RX Supply 1.8V and 1.15V (C191.1 L25.2)
GND: Sht01--EVM_Hardware (40 pins), Sht02--Input Output Connector (77 pins), Sht03--Efuse_Power on-Off Controller (54 pins), Sht04--FPGA Power Supply (51 pins), Sht05--TX-RX Supply 1.8V and 1.15V (59 pins), Sht06--TX Supply +5V and -5V (37 pins), Sht07--High Voltage Power Supply (22 pins)
MHV: Sht02--Input Output Connector (P1.79 P1.80), Sht07--High Voltage Power Supply (C17.2 L6.2)
PHV: Sht02--Input Output Connector (P2.79 P2.80), Sht07--High Voltage Power Supply (C13.1 L4.2)
USB_5V: Sht02--Input Output Connector (6 pins), Sht03--Efuse_Power on-Off Controller (R116.1 R146.2)
VBUS: Sht02--Input Output Connector (7 pins), Sht03--Efuse_Power on-Off Controller (6 pins), Sht04--FPGA Power Supply (5 pins), Sht05--TX-RX Supply 1.8V and 1.15V (9 pins), Sht06--TX Supply +5V and -5V (R91.1 R105.1), Sht07--High Voltage Power Supply (5 pins)
VCC_AUX_1V8: Sht02--Input Output Connector (C50.1 L9.1 P1.20 P1.22), Sht03--Efuse_Power on-Off Controller (R148.2 R149.2), Sht04--FPGA Power Supply (C86.1 L15.2 R72.2 R73.2), Sht07--High Voltage Power Supply (R26.1 R27.1 R32.2 R33.2)
VCC_INT_1V: Sht02--Input Output Connector (P1.33 P1.34 P1.35 P1.36), Sht04--FPGA Power Supply (C87.1 L13.2)
VCCO_2V5: Sht02--Input Output Connector (C47.1 L8.1 P1.48 P1.50), Sht04--FPGA Power Supply (C57.1 L11.2)
VDDM_LV5: Sht02--Input Output Connector (P1.67 P1.69), Sht06--TX Supply +5V and -5V (C117.1 L18.2)
VDDP_LV5: Sht02--Input Output Connector (6 pins), Sht06--TX Supply +5V and -5V (C107.1 L17.2)
DC_DC_CLK1: Sht02--Input Output Connector (P1.43 R37.2), Sht06--TX Supply +5V and -5V (R111.1)
DM_USB: Sht02--Input Output Connector (P1.28), Sht03--Efuse_Power on-Off Controller (D12.1 U18.F3)
DP_USB: Sht02--Input Output Connector (P1.26), Sht03--Efuse_Power on-Off Controller (D11.1 U18.F2)
FPGA_PG_1V: Sht02--Input Output Connector (R60.1), Sht04--FPGA Power Supply (D5.2 U13.14)
FPGA_PG_1V8: Sht02--Input Output Connector (R43.1), Sht04--FPGA Power Supply (D6.2 U14.14)
FPGA_PG_2V5: Sht02--Input Output Connector (R54.1), Sht04--FPGA Power Supply (D4.2 U11.14)
GLOBAL ENABLE: Sht02--Input Output Connector (P1.44), Sht05--TX-RX Supply 1.8V and 1.15V (R161.1 R173.1), Sht06--TX Supply +5V and -5V (R94.1 R110.1), Sht07--High Voltage Power Supply (R8.1)
HV DISABLE: Sht02--Input Output Connector (P1.40), Sht07--High Voltage Power Supply (R21.1)
HV_PG: Sht02--Input Output Connector (R42.1), Sht07--High Voltage Power Supply (D3.2 U1.4)
RX_PG_1V2: Sht02--Input Output Connector (R61.1), Sht05--TX-RX Supply 1.8V and 1.15V (D14.2 U27.14)
RX_PG_1V8: Sht02--Input Output Connector (R46.1), Sht05--TX-RX Supply 1.8V and 1.15V (D7.2 U25.14)
SCL: Sht02--Input Output Connector (P2.45 R38.1 R44.2 SCL.1), Sht03--Efuse_Power on-Off Controller (R148.1 R193.1 U23.A1), Sht04--FPGA Power Supply (R73.1 U12.A1), Sht07--High Voltage Power Supply (R27.2 R32.1 U2.2 U3.A1)
SDA: Sht02--Input Output Connector (P2.46 R39.1 R45.2 SDA.1), Sht03--Efuse_Power on-Off Controller (R16.1 R149.1 U23.A2), Sht04--FPGA Power Supply (R72.1 U12.A2), Sht07--High Voltage Power Supply (R26.2 R33.1 U2.3 U3.A2)
SYNC_1V2_RX: Sht02--Input Output Connector (R50.1), Sht05--TX-RX Supply 1.8V and 1.15V (R187.2)
SYNC_1V8_FX3: Sht02--Input Output Connector (R57.1), Sht04--FPGA Power Supply (R191.2)
SYNC_1V8_RX: Sht02--Input Output Connector (R53.1), Sht05--TX-RX Supply 1.8V and 1.15V (R186.2)
SYNC_5V_TX: Sht02--Input Output Connector (R56.1), Sht06--TX Supply +5V and -5V (R192.1)
SYNC_-5V_TX: Sht02--Input Output Connector (R55.1), Sht06--TX Supply +5V and -5V (C124.2 R111.2)
SYNC_FPGA_1V: Sht02--Input Output Connector (R58.1), Sht04--FPGA Power Supply (R190.2)
SYNC_FPGA_2V5: Sht02--Input Output Connector (R59.1), Sht04--FPGA Power Supply (R189.2)
SYNC_HV_TX: Sht02--Input Output Connector (R47.1), Sht07--High Voltage Power Supply (R12.1)

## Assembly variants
001: not fitted C25 C26 C150 C154 C155 J2 L24 L28 L29 R3 R8 R40 R49 R92 R104 R106 R110 R111 R117 R132 R150 R152 R153 R154 R161 R173 R184 R195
